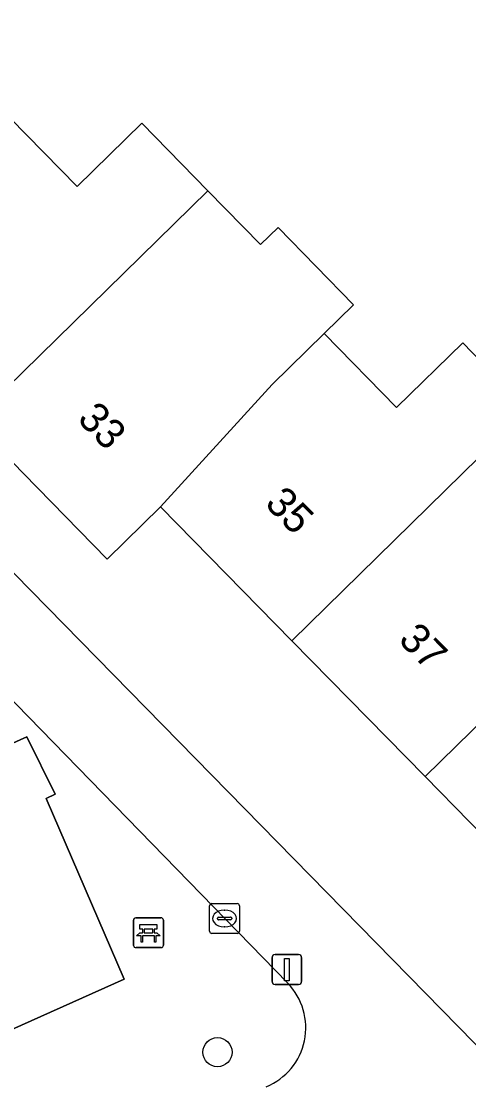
# Model space of a CAD drawing. Extents: x 162879 to 165540, y 384011 to 385181.
# Drawn here: x 164101.17 to 164116.16, y 384229.44 to 384265.17 of the extents above; entities that cross this region are included whole.
import ezdxf

# ---------------------------------------------------------------- set-up
doc = ezdxf.new("R2010")
doc.units = 0
for name, color, linetype in [('IMGEO_Bank', 7, 'Continuous'), ('IMGEO_Boom', 7, 'Continuous'), ('IMGEO_Erf', 7, 'Continuous'), ('IMGEO_Groenvoorziening', 7, 'Continuous'), ('IMGEO_Kolk', 7, 'Continuous'), ('IMGEO_Lichtmast', 7, 'Continuous'), ('IMGEO_Pand', 7, 'Continuous'), ('IMGEO_Pand_nummerreeks', 7, 'Continuous'), ('IMGEO_Terreindeel_zand', 7, 'Continuous'), ('IMGEO_Voetpad_open', 7, 'Continuous')]:
    doc.layers.add(name, color=color, linetype=linetype)

msp = doc.modelspace()

# ---------------------------------------------------------------- linework, layer by layer
at = {"layer": 'IMGEO_Bank'}
for p, q in [((164105.004, 384235.106), (164105.845, 384235.106)), ((164105.845, 384235.106), (164105.004, 384235.106)), ((164104.929, 384234.181), (164104.929, 384235.022)), ((164104.929, 384235.022), (164104.929, 384234.181)), ((164105.238, 384234.612), (164105.238, 384234.718)), ((164105.282, 384234.718), (164105.282, 384234.612)), ((164105.57, 384234.724), (164105.288, 384234.724)), ((164105.576, 384234.612), (164105.576, 384234.718)), ((164105.62, 384234.718), (164105.62, 384234.612)), ((164105.929, 384235.031), (164105.929, 384234.19)), ((164105.929, 384234.19), (164105.929, 384235.031)), ((164105.626, 384234.504), (164105.233, 384234.504)), ((164105.288, 384234.606), (164105.57, 384234.606)), ((164105.854, 384234.106), (164105.013, 384234.106)), ((164105.013, 384234.106), (164105.854, 384234.106))]:
    msp.add_line(p, q, dxfattribs=at)
for points in [[(164105.232, 384234.724), (164105.146, 384234.724), (164105.146, 384234.885), (164105.709, 384234.885), (164105.709, 384234.724), (164105.626, 384234.724)], [(164105.176, 384234.504), (164105.034, 384234.504), (164105.146, 384234.606), (164105.232, 384234.606)], [(164105.226, 384234.497), (164105.226, 384234.29), (164105.183, 384234.29), (164105.183, 384234.497)], [(164105.626, 384234.606), (164105.709, 384234.606), (164105.821, 384234.504), (164105.682, 384234.504)], [(164105.676, 384234.497), (164105.676, 384234.29), (164105.632, 384234.29), (164105.632, 384234.497)]]:
    msp.add_lwpolyline(points, dxfattribs=at)
for centre, radius, start, end in [((164105.007, 384235.028), 0.0779, 92.4484, 184.2845), ((164105.007, 384235.028), 0.0779, 92.4484, 184.2845), ((164105.851, 384235.028), 0.0779, 2.4484, 94.2845), ((164105.851, 384235.028), 0.0779, 2.4484, 94.2845), ((164105.231, 384234.717), 0.00671, 2.8957, 87.1043), ((164105.288, 384234.717), 0.00671, 92.8957, 177.1043), ((164105.57, 384234.717), 0.00671, 2.8957, 87.1043), ((164105.627, 384234.717), 0.00671, 92.8957, 177.1043), ((164105.176, 384234.497), 0.00671, 2.8957, 87.1043), ((164105.233, 384234.497), 0.00671, 92.8957, 177.1043), ((164105.231, 384234.613), 0.00671, 272.8957, 357.1043), ((164105.288, 384234.613), 0.00671, 182.8957, 267.1043), ((164105.57, 384234.613), 0.00671, 272.8957, 357.1043), ((164105.627, 384234.613), 0.00671, 182.8957, 267.1043), ((164105.625, 384234.497), 0.00671, 2.8957, 87.1043), ((164105.682, 384234.497), 0.00671, 92.8957, 177.1043), ((164105.007, 384234.184), 0.0779, 182.4484, 274.2845), ((164105.007, 384234.184), 0.0779, 182.4484, 274.2845), ((164105.851, 384234.184), 0.0779, 272.4484, 4.2845), ((164105.851, 384234.184), 0.0779, 272.4484, 4.2845)]:
    msp.add_arc(centre, radius, start, end, dxfattribs=at)
at = {"layer": 'IMGEO_Boom'}
msp.add_circle((164107.743, 384230.599), 0.489, dxfattribs=at)
at = {"layer": 'IMGEO_Erf'}
for points in [[(164100.566, 384266.508), (164098.393, 384264.385), (164100.798, 384261.923), (164103.04, 384259.629), (164105.211, 384261.75), (164107.42, 384259.489), (164109.189, 384257.679), (164109.774, 384258.25), (164112.3, 384255.666), (164111.316, 384254.701), (164113.746, 384252.214), (164115.964, 384254.382), (164118.137, 384252.139)], [(164119.164, 384235.288), (164114.701, 384239.843), (164110.239, 384244.396), (164105.836, 384248.888), (164104.047, 384247.134), (164101.247, 384250), (164099.531, 384251.756), (164095.078, 384256.314), (164090.485, 384261.015), (164092.274, 384262.763), (164089.297, 384265.81)], [(164087.86, 384259.97), (164097.631, 384250), (164124.609, 384222.474), (164121.025, 384221.682)]]:
    msp.add_lwpolyline(points, dxfattribs=at)
at = {"layer": 'IMGEO_Groenvoorziening'}
msp.add_lwpolyline([(164110.095, 384232.91), (164099.747, 384243.542), (164094.021, 384241.732), (164092.956, 384241.395)], dxfattribs=at)
msp.add_lwpolyline([(164095.246, 384237.595), (164098.907, 384239.168), (164098.613, 384239.942), (164101.359, 384241.171), (164102.299, 384239.25), (164101.997, 384239.11), (164104.613, 384233.049), (164098.376, 384230.254)], close=True, dxfattribs=at)
msp.add_arc((164108.566, 384231.418), 2.137, 292.3491, 44.2886, dxfattribs=at)
at = {"layer": 'IMGEO_Kolk'}
for p, q in [((164107.48, 384234.656), (164107.48, 384235.508)), ((164107.555, 384235.582), (164108.407, 384235.582)), ((164108.481, 384235.508), (164108.481, 384234.656)), ((164107.739, 384235.076), (164107.739, 384235.088)), ((164107.782, 384235.125), (164108.18, 384235.125)), ((164107.968, 384235.362), (164107.993, 384235.362)), ((164108.223, 384235.088), (164108.223, 384235.076)), ((164108.177, 384235.039), (164107.779, 384235.039)), ((164107.991, 384234.802), (164107.966, 384234.802)), ((164108.407, 384234.582), (164107.555, 384234.582))]:
    msp.add_line(p, q, dxfattribs=at)
for points in [[(164107.48, 384234.656), (164107.48, 384235.508)], [(164107.555, 384235.582), (164108.407, 384235.582)], [(164108.481, 384235.508), (164108.481, 384234.656)], [(164108.407, 384234.582), (164107.555, 384234.582)]]:
    msp.add_lwpolyline(points, dxfattribs=at)
for centre, radius, start, end in [((164107.557, 384235.506), 0.0765, 91.552, 178.448), ((164107.557, 384235.506), 0.0765, 91.552, 178.448), ((164108.405, 384235.506), 0.0765, 1.552, 88.448), ((164108.405, 384235.506), 0.0765, 1.552, 88.448), ((164107.779, 384235.085), 0.0403, 85.8775, 175.7526), ((164107.776, 384235.075), 0.0366, 178.938, 274.7102), ((164108.18, 384235.082), 0.043, 264.8664, 352.4533), ((164108.184, 384235.087), 0.0386, 1.7309, 96.639), ((164107.557, 384234.658), 0.0765, 181.552, 268.448), ((164107.557, 384234.658), 0.0765, 181.552, 268.448), ((164108.405, 384234.658), 0.0765, 271.552, 358.448), ((164108.405, 384234.658), 0.0765, 271.552, 358.448)]:
    msp.add_arc(centre, radius, start, end, dxfattribs=at)
for centre, major_axis, ratio, start_param, end_param in [((164107.967, 384235.082), (-0.387, 0.002), 0.722429, 4.712389, 7.853982), ((164107.992, 384235.082), (-0.39, 0.002), 0.717154, 1.570796, 4.712389)]:
    msp.add_ellipse(centre, major_axis=major_axis, ratio=ratio, start_param=start_param, end_param=end_param, dxfattribs=at)
at = {"layer": 'IMGEO_Lichtmast'}
for p, q in [((164109.572, 384232.97), (164109.572, 384233.77)), ((164109.572, 384233.77), (164109.572, 384232.97)), ((164109.672, 384233.87), (164110.462, 384233.87)), ((164110.462, 384233.87), (164109.672, 384233.87)), ((164110.562, 384233.77), (164110.562, 384232.97)), ((164110.562, 384232.97), (164110.562, 384233.77)), ((164110.462, 384232.87), (164109.672, 384232.87)), ((164109.672, 384232.87), (164110.462, 384232.87))]:
    msp.add_line(p, q, dxfattribs=at)
msp.add_lwpolyline([(164109.992, 384233.745), (164110.142, 384233.745), (164110.142, 384232.995), (164109.992, 384232.995), (164109.992, 384233.745)], dxfattribs=at)
for centre, start, end in [((164109.672, 384233.77), 90, 180), ((164109.672, 384233.77), 90, 180), ((164110.462, 384233.77), 0, 90), ((164110.462, 384233.77), 360, 90), ((164109.672, 384232.97), 180, 270), ((164109.672, 384232.97), 180, 270), ((164110.462, 384232.97), 270, 0), ((164110.462, 384232.97), 270, 0)]:
    msp.add_arc(centre, 0.1, start, end, dxfattribs=at)
at = {"layer": 'IMGEO_Pand'}
for points in [[(164107.42, 384259.489), (164105.211, 384261.75), (164103.04, 384259.629), (164100.798, 384261.923), (164095.078, 384256.314), (164099.531, 384251.756)], [(164111.316, 384254.701), (164112.3, 384255.666), (164109.774, 384258.25), (164109.189, 384257.679), (164107.42, 384259.489), (164099.531, 384251.756), (164101.247, 384250), (164104.047, 384247.134), (164105.836, 384248.888), (164109.574, 384252.993)], [(164110.239, 384244.396), (164115.955, 384250), (164118.137, 384252.139), (164115.964, 384254.382), (164113.746, 384252.214), (164111.316, 384254.701), (164109.574, 384252.993), (164105.836, 384248.888)], [(164110.239, 384244.396), (164114.701, 384239.843), (164120.406, 384245.435), (164118.037, 384247.852), (164120.21, 384250), (164118.137, 384252.139), (164115.955, 384250)], [(164127.054, 384243.023), (164124.94, 384245.18), (164122.591, 384247.577), (164120.406, 384245.435), (164114.701, 384239.843), (164119.164, 384235.288)]]:
    msp.add_lwpolyline(points, close=True, dxfattribs=at)
at = {"layer": 'IMGEO_Terreindeel_zand'}
msp.add_lwpolyline([(164104.613, 384233.049), (164101.997, 384239.11), (164102.299, 384239.25), (164101.359, 384241.171), (164098.613, 384239.942), (164098.907, 384239.168), (164095.246, 384237.595), (164098.376, 384230.254)], close=True, dxfattribs=at)
at = {"layer": 'IMGEO_Voetpad_open'}
for points in [[(164121.025, 384221.682), (164124.609, 384222.474), (164097.631, 384250), (164087.86, 384259.97)], [(164085.735, 384257.978), (164093.476, 384250), (164098.263, 384245.067), (164099.747, 384243.542), (164110.095, 384232.91)]]:
    msp.add_lwpolyline(points, dxfattribs=at)
msp.add_arc((164108.566, 384231.418), 2.137, 292.3491, 44.2886, dxfattribs=at)

# ---------------------------------------------------------------- texts
at = {"layer": 'IMGEO_Pand_nummerreeks'}
for s, rotation, p in [('33', 314.3353, (164103.011, 384251.799)), ('35', 314.4221, (164109.295, 384248.959)), ('37', 314.4221, (164113.77, 384244.392))]:
    msp.add_text(s, height=1, rotation=rotation, dxfattribs=at).set_placement(p)

doc.saveas('drawing.dxf')
